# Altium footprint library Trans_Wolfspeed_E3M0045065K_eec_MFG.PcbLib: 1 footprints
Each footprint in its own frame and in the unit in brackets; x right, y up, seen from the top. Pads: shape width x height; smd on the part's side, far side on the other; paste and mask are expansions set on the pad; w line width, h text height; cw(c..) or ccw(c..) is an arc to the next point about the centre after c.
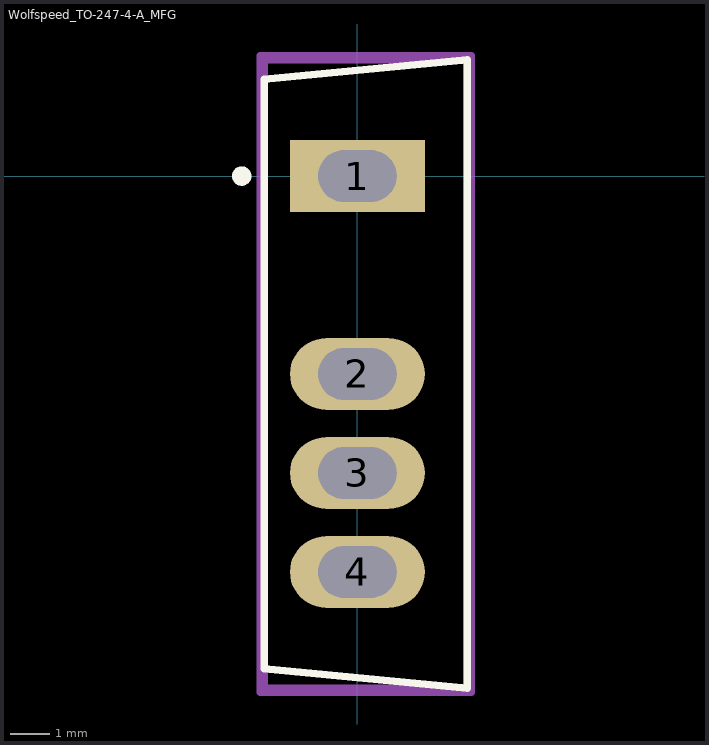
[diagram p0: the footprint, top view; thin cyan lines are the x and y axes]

## Wolfspeed_TO-247-4-A_MFG [mm]
pads (4):
  rect 3.46x1.84 hole 1.33 slot 2.01 at 0 deg paste-1000 mask+0: 1(0,0)
  rrect100% 3.46x1.84 hole 1.33 slot 2.01 at 0 deg paste-1000 mask+0: 2(0,-5.08) 3(0,-7.62) 4(0,-10.16)
Top Overlay:
  circle w0.25: c-2.967,0 r0.125
  lines w0.2: -2.392,-12.645 2.818,-13.145 2.818,2.985 -2.392,2.485 -2.392,-12.645
Mechanical 10:
  lines w0.2: -2.492,-13.245 2.917,-13.245 2.917,3.085 -2.492,3.085 -2.492,-13.245
  text ".Designator" at 0.212,-4.892 h1
Mechanical 12:
  lines w0.2: -2.392,-13.145 2.818,-13.145 2.818,2.985 -2.392,2.985 -2.392,-13.145
Mechanical 15:
  lines w0.1: -0.5,0 0.5,0 ; 0,-0.5 0,0.5
  lines w0.2: -2.492,-13.245 2.917,-13.245 2.917,3.085 -2.492,3.085 -2.492,-13.245
3D body "Trans_Wolfspeed_E3M0045065K_eec.STEP": height 0.25, standoff 0, extent -2.492,-13.245 2.917,3.085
